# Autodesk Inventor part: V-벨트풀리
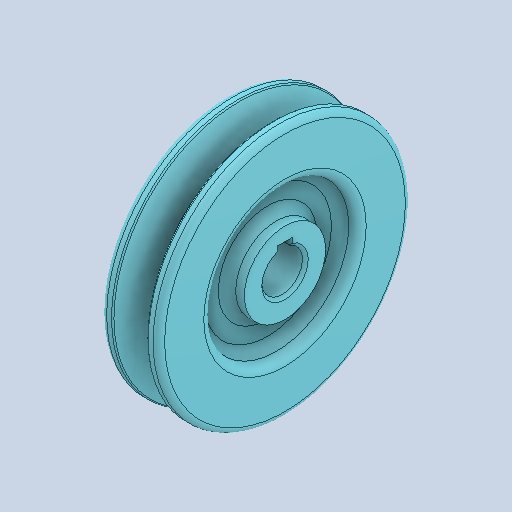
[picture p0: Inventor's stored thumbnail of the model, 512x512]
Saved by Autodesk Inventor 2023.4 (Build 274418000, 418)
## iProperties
Created: 2024-04
Part Number: V-벨트풀리
Material: 일반
Document SubType Name: Modeling
Designer: EDU
Density: 1 g/cm^3
Appearance: 기본값
Author: jhkim
Sending System: Autodesk Inventor 2025
Preprocessor: ST-DEVELOPER v20
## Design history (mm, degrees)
node "V-벨트풀리1"
node "솔리드2"
node "솔리드1"
